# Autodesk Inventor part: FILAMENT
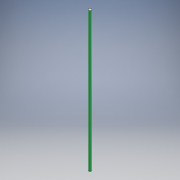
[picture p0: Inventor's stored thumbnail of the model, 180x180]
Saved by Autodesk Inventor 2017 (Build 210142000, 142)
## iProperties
Created: 2021-01
Part Number: FILAMENT
Material: Generic
Document SubType Name: Modeling
Designer: WindowsX
Density: 1 g/cm^3
Appearance: Default
Author: WindowsX
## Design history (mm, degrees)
sketch "Szkic1"
  geometry: C1 r 0.875 at (0, 0); 1 further point
  constraints: 1 centre point, 1 coincident
  dimensions: "d0" = 1.75 diameter of C1
extrude "Wyciągnięcie proste1" new body sketch "Szkic1" distance "d1" = 100; taper "d2" = 0 deg
node "Bryła1"
